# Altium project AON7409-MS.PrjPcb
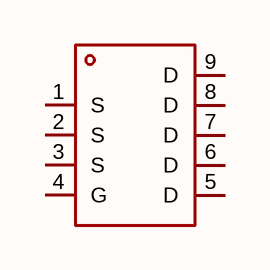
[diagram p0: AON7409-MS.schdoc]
1 sheet, 1 parts. Net scope: global (net labels, ports and power ports of the same name join across sheets).

## Sheet AON7409-MS.schdoc
size 127 x 101 mm

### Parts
Q?  aon7409-ms  [PDFN-8_L4.9-W5.8-P1.27-LS6.1-BL]  (value not drawn)

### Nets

Not connected (* = marked no-connect by the designer): Q? 1(S) 2(S) 3(S) 4(G) 5(D) 6(D) 7(D) 8(D) 9(D)

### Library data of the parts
Q? = aon7409-ms: 数量:1个P沟道;漏源电压(Vdss):30V;连续漏极电流(Id):70A;导通电阻(RDS(on)):6mΩ@10V;耗散功率(Pd):31.2W;阈值电压(Vgs(th)):1.6V;; Manufacturer: MSKSEMI(美森科); AddInBom: yes; ModelId: 178189b27e7544aca50c111426555358; ModelName: PDFN-8_L4.9-W5.8-H1.0-P1.27; ModelTransform: 200.787,240.157,0,0,0,0,-0.097,0,0; Number: 1个P沟道; Drain to Source Voltage: 30V; Current - Continuous Drain(Id): 70A; Pd - Power Dissipation: 31.2W; Gate Threshold Voltage (Vgs(th)): 1.6V; Gate Charge(Qg): 45nC; Input Capacitance(Ciss): 4.32nF; Reverse Transfer Capacitance (Crss@Vds): 487pF; Type: P沟道; Output Capacitance(Coss): 529pF; Vgs: ±20V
